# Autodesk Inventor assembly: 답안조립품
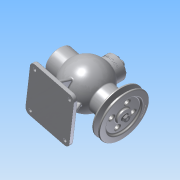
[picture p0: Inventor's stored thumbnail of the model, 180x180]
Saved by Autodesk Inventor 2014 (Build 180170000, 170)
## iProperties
Created: 2017-01
Part Number: 답안조립품
Document SubType Name: Assembly
Designer: ksu
Author: ksu
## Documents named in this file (19)
- C:\Users\ksu\Desktop\470118V1003\470118V1003\답안조립품.iam
- C:\Users\ksu\Desktop\470118V1003\470118V1003\V-벨트풀리.ipt
- C:\Users\ksu\Desktop\470118V1003\470118V1003\뒤커버.ipt
- C:\Users\ksu\Desktop\470118V1003\470118V1003\본체.ipt
- C:\Users\ksu\Desktop\470118V1003\470118V1003\부시.ipt
- C:\Users\ksu\Desktop\470118V1003\470118V1003\상부커버.ipt
- C:\Users\ksu\Desktop\470118V1003\470118V1003\슬라이드.ipt
- C:\Users\ksu\Desktop\470118V1003\470118V1003\앞커버.ipt
- C:\Users\ksu\Desktop\470118V1003\470118V1003\편심축.ipt
- C:\Users\ksu\Desktop\470118V1003\470118V1003\베어링- 6202.ipt
- KS B 2023 - 6202 - 15 x 35 x 11 - 7.8.ipt
- C:\Users\ksu\Desktop\470118V1003\470118V1003\오일실 15 30 7.ipt
- C:\Users\ksu\Desktop\470118V1003\470118V1003\너트 M8.ipt
- C:\Users\ksu\Desktop\470118V1003\470118V1003\멈춤링- 15 x 1.ipt
- C:\Users\ksu\Desktop\470118V1003\470118V1003\멈춤링- 35x1.6.ipt
- KS B 1336 - 35x1.6.ipt
- C:\Users\ksu\Desktop\470118V1003\470118V1003\볼트 M4 x 16.ipt
- C:\Users\ksu\Desktop\470118V1003\470118V1003\키 4 x 4 x 12.ipt
- C:\Users\ksu\Desktop\470118V1003\470118V1003\볼트 M4 x 12.ipt
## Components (16 placed, 5 different names)
1. V-벨트풀리:1 — Mate:1, Mate:11, Mate:50
2. KS B 2023 - 6202 - 15 x 35 x 11 - 7.8:1 — Mate:6, Mate:8, Mate:9
3. KS B 1336 - 35x1.6:1 — Mate:25, Mate:26
4. KS B 2023 - 6202 - 15 x 35 x 11 - 7.8:2 — Mate:17, Mate:18, Mate:19
5. ISO 4762 M4 x 16:1 — Mate:32, Mate:36
6. ISO 4762 M4 x 16:2 — Mate:34, Mate:37
7. ISO 4762 M4 x 16:3 — Mate:33, Mate:38
8. ISO 4762 M4 x 16:4 — Mate:31, Mate:35
9. ISO 4762 M4 x 16:5 — Mate:42, Mate:47
10. ISO 4762 M4 x 16:6 — Mate:44, Mate:48
11. ISO 4762 M4 x 16:7 — Mate:43, Mate:46
12. ISO 4762 M4 x 16:8 — Mate:45, Mate:49
13. KS B 1021 - 에 따름 ISO 1207 - 미터 A  M 4 x 12:1 — Mate:53, Mate:56
14. KS B 1021 - 에 따름 ISO 1207 - 미터 A  M 4 x 12:2 — Mate:54, Mate:59
15. KS B 1021 - 에 따름 ISO 1207 - 미터 A  M 4 x 12:3 — Mate:51, Mate:57
16. KS B 1021 - 에 따름 ISO 1207 - 미터 A  M 4 x 12:4 — Mate:52, Mate:58
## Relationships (35: Mate 35)
- Mate:1: V-벨트풀리:1
- Mate:6: KS B 2023 - 6202 - 15 x 35 x 11 - 7.8:1
- Mate:8: KS B 2023 - 6202 - 15 x 35 x 11 - 7.8:1
- Mate:9: KS B 2023 - 6202 - 15 x 35 x 11 - 7.8:1
- Mate:11: V-벨트풀리:1
- Mate:17: KS B 2023 - 6202 - 15 x 35 x 11 - 7.8:2
- Mate:18: KS B 2023 - 6202 - 15 x 35 x 11 - 7.8:2
- Mate:19: KS B 2023 - 6202 - 15 x 35 x 11 - 7.8:2
- Mate:25: KS B 1336 - 35x1.6:1
- Mate:26: KS B 1336 - 35x1.6:1
- Mate:31: ISO 4762 M4 x 16:4
- Mate:32: ISO 4762 M4 x 16:1
- Mate:33: ISO 4762 M4 x 16:3
- Mate:34: ISO 4762 M4 x 16:2
- Mate:35: ISO 4762 M4 x 16:4
- Mate:36: ISO 4762 M4 x 16:1
- Mate:37: ISO 4762 M4 x 16:2
- Mate:38: ISO 4762 M4 x 16:3
- Mate:42: ISO 4762 M4 x 16:5
- Mate:43: ISO 4762 M4 x 16:7
- Mate:44: ISO 4762 M4 x 16:6
- Mate:45: ISO 4762 M4 x 16:8
- Mate:46: ISO 4762 M4 x 16:7
- Mate:47: ISO 4762 M4 x 16:5
- Mate:48: ISO 4762 M4 x 16:6
- Mate:49: ISO 4762 M4 x 16:8
- Mate:50: V-벨트풀리:1
- Mate:51: KS B 1021 - 에 따름 ISO 1207 - 미터 A  M 4 x 12:3
- Mate:52: KS B 1021 - 에 따름 ISO 1207 - 미터 A  M 4 x 12:4
- Mate:53: KS B 1021 - 에 따름 ISO 1207 - 미터 A  M 4 x 12:1
- Mate:54: KS B 1021 - 에 따름 ISO 1207 - 미터 A  M 4 x 12:2
- Mate:56: KS B 1021 - 에 따름 ISO 1207 - 미터 A  M 4 x 12:1
- Mate:57: KS B 1021 - 에 따름 ISO 1207 - 미터 A  M 4 x 12:3
- Mate:58: KS B 1021 - 에 따름 ISO 1207 - 미터 A  M 4 x 12:4
- Mate:59: KS B 1021 - 에 따름 ISO 1207 - 미터 A  M 4 x 12:2
